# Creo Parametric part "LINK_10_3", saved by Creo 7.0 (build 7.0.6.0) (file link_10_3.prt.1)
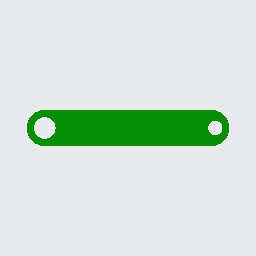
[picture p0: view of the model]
Units: millimeter Newton Second (mmNs); MM, TONNE, SECS

Created from: XX_MMNS_PART_SOLID_ABS.PRT

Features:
  1. datum plane "RIGHT"
  2. datum plane "TOP"
  3. datum plane "FRONT"
  4. coordinate system
  5. extrusion "Extrude 1"
  6. extruded cut "Extrude 2"
  7. extruded cut "Extrude 3"

Surfaces: 4 plane, 4 cylinder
